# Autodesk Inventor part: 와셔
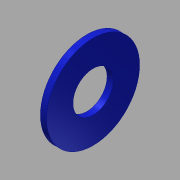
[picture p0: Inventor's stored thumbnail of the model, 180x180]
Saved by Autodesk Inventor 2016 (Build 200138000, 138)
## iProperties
Created: 2015-12
Part Number: 와셔
Material: 스테인리스강
Document SubType Name: Modeling
Designer: mduedu
Density: 8.08 g/cm^3
Appearance: 파란색 - 벽 페인트 - 광택
Author: mduedu
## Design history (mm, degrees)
sketch "스케치1"
  geometry: C1 r 3.25 at (0, 0); C2 r 7.5 at (0, 0); 1 further point
  constraints: 2 centre point, 2 coincident
  dimensions: "d0" = 6.5 diameter of C1; "d1" = 15 diameter of C2
extrude "돌출1" new body sketch "스케치1" stored distance "d2" = 1; taper "d3" = 0 deg
node "솔리드1"
